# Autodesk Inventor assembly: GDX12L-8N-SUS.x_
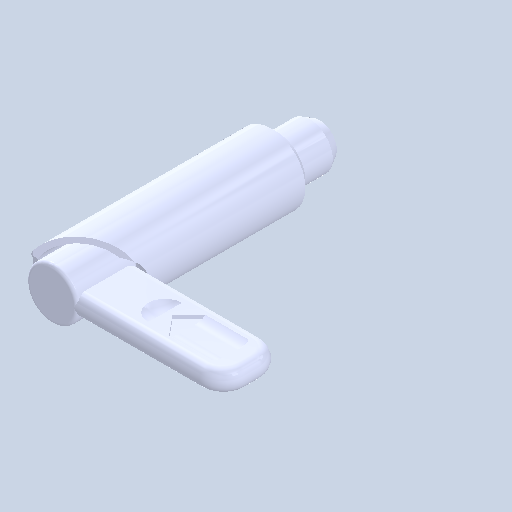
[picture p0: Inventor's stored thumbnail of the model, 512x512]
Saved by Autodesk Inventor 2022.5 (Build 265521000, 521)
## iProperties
Created: 2024-06
Part Number: GDX12L-8N-SUS.x_
Document SubType Name: Assembly
Designer: ImaoCorp
Author: ImaoCorp
Sending System: SOLIDWORKS 2022-2022290
MC: AMD64
MC_MODEL: Intel64 Family 6 Model 60 Stepping 3, GenuineIntel
OS: Windows_NT
FRU: Parasolid Version 33.1, build 260,  4-25-2022
FORMAT: text
GUISE: transmit
KEY: FILEGDX12L-8N-SUS.x_t
DATE: Wed Jun 12 09:31:53 2024
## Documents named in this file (3)
- Y:\5.更新分\2024年対応\xxxx_GDX\データ_imao品番\gdx12l-8n-sus\GDX12L-8N-SUS.x_.iam
- Y:\5.更新分\2024年対応\xxxx_GDX\データ_imao品番\gdx12l-8n-sus\GDX12L-8N-SUS_01.ipt
- Y:\5.更新分\2024年対応\xxxx_GDX\データ_imao品番\gdx12l-8n-sus\GDX12L-8N-SUS_02.ipt
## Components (2 placed, 2 different names)
1. GDX12L-8N-SUS_01
2. GDX12L-8N-SUS_02
